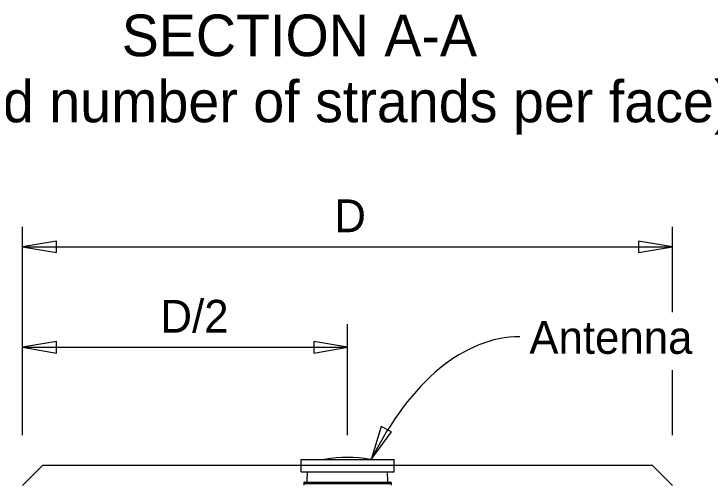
# Model space of a CAD drawing. Extents: x 0 to 36.1, y -3.7 to 15.
# Drawn here: x 2.266 to 4.409, y 4.351 to 5.799 of the extents above; entities that cross this region are included whole.
import ezdxf

# ---------------------------------------------------------------- set-up
doc = ezdxf.new("R2010")
doc.units = 0
for name, color, linetype in [('AdhocPoint_dp', 7, 'Continuous'), ('Leader', 7, 'Continuous'), ('Miscellaneous', 7, 'Continuous'), ('PileConc', 7, 'Continuous'), ('PlotBorder_dp', 7, 'Continuous')]:
    doc.layers.add(name, color=color, linetype=linetype)

msp = doc.modelspace()

# ---------------------------------------------------------------- linework, layer by layer
at = {"layer": 'Leader'}
msp.add_ellipse((3.8235, 3.4979), major_axis=(0, -1.3086), ratio=0.497877, start_param=3.141593, end_param=3.920397, dxfattribs=at)
at = {"layer": 'Miscellaneous'}
for p, q in [((3.1499, 4.4293), (3.1915, 4.4293)), ((3.1499, 4.4118), (3.1499, 4.4293)), ((3.1915, 4.4293), (3.3946, 4.4293)), ((3.2228, 4.4294), (3.2228, 4.4293)), ((3.3633, 4.4294), (3.3633, 4.4293)), ((3.3946, 4.4293), (3.4362, 4.4293)), ((3.4362, 4.4118), (3.4362, 4.4293)), ((3.1499, 4.391), (3.1499, 4.4118)), ((3.1499, 4.4118), (3.1915, 4.4118)), ((3.1915, 4.4118), (3.3946, 4.4118)), ((3.3946, 4.4118), (3.4362, 4.4118)), ((3.4362, 4.391), (3.4362, 4.4118)), ((3.1499, 4.391), (3.1915, 4.391)), ((3.1693, 4.361), (3.1701, 4.391)), ((3.1915, 4.391), (3.3946, 4.391)), ((3.3946, 4.391), (3.4362, 4.391)), ((3.4167, 4.361), (3.416, 4.391)), ((3.159, 4.3585), (3.1589, 4.3545)), ((3.1915, 4.3545), (3.1589, 4.3545)), ((3.1589, 4.3545), (3.159, 4.3505)), ((3.1603, 4.3597), (3.1915, 4.3597)), ((3.1915, 4.3597), (3.3946, 4.3597)), ((3.3946, 4.3545), (3.1915, 4.3545)), ((3.3946, 4.3597), (3.4258, 4.3597)), ((3.4272, 4.3545), (3.3946, 4.3545)), ((3.4271, 4.3585), (3.4272, 4.3545)), ((3.4272, 4.3545), (3.4271, 4.3505))]:
    msp.add_line(p, q, dxfattribs=at)
for centre, radius, start, end in [((3.293, 4.0317), 0.4038, 79.9853, 100.0147), ((3.293, 4.0317), 0.4038, 100.0147, 100.0917), ((3.293, 4.0317), 0.4038, 79.9083, 79.9853), ((3.1603, 4.3585), 0.00125, 90, 178.5), ((3.1681, 4.361), 0.00125, 270, 358.5), ((3.418, 4.361), 0.00125, 181.5, 270), ((3.4258, 4.3585), 0.00125, 1.5, 90)]:
    msp.add_arc(centre, radius, start, end, dxfattribs=at)
at = {"layer": 'PileConc'}
for p, q in [((2.293, 4.3493), (2.3555, 4.4118)), ((2.3555, 4.4118), (4.2305, 4.4118)), ((4.2305, 4.4118), (4.293, 4.3493))]:
    msp.add_line(p, q, dxfattribs=at)
at = {"layer": 'PlotBorder_dp'}
for p, q in [((2.293, 4.5036), (2.293, 5.1448)), ((4.293, 4.8819), (4.293, 5.1448)), ((2.293, 5.083), (4.293, 5.083)), ((3.293, 4.5036), (3.293, 4.8451)), ((2.293, 4.7742), (3.293, 4.7742)), ((4.293, 4.5036), (4.293, 4.7034))]:
    msp.add_line(p, q, dxfattribs=at)
for points in [[(2.293, 5.083), (2.3972, 5.0654), (2.3972, 5.1006)], [(4.293, 5.083), (4.1889, 5.1006), (4.1889, 5.0654)], [(2.293, 4.7742), (2.3972, 4.7566), (2.3972, 4.7918)], [(3.293, 4.7742), (3.1889, 4.7918), (3.1889, 4.7566)], [(3.3658, 4.4293), (3.4285, 4.5143), (3.397, 4.5302)]]:
    msp.add_lwpolyline(points, close=True, dxfattribs=at)

# ---------------------------------------------------------------- texts
at = {"layer": 'AdhocPoint_dp'}
for s, height, p in [('SECTION A-A', 0.128, (2.598, 5.6693)), ('(Strand Pattern with odd number of strands per face)', 0.128, (0.4817, 5.4661)), ('D', 0.1008, (3.2524, 5.128)), ('D/2', 0.1008, (2.7171, 4.8192))]:
    msp.add_text(s, height=height, dxfattribs=at).set_placement(p)
at = {"layer": 'PlotBorder_dp'}
msp.add_text('Antenna', height=0.1008, dxfattribs=at).set_placement((3.8526, 4.7541))

doc.saveas('drawing.dxf')
